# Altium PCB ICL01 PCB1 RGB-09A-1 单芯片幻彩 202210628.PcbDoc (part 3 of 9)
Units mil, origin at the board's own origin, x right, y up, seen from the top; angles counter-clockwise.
Board outline 17436.43 x 6581.89 mil, 2 copper layers (Top Layer, Bottom Layer), stack 65.792 mil thick; 425 components, 516 nets, 1625 pads, 2772 vias.
Unrouted connection lines stored in the file: 1.
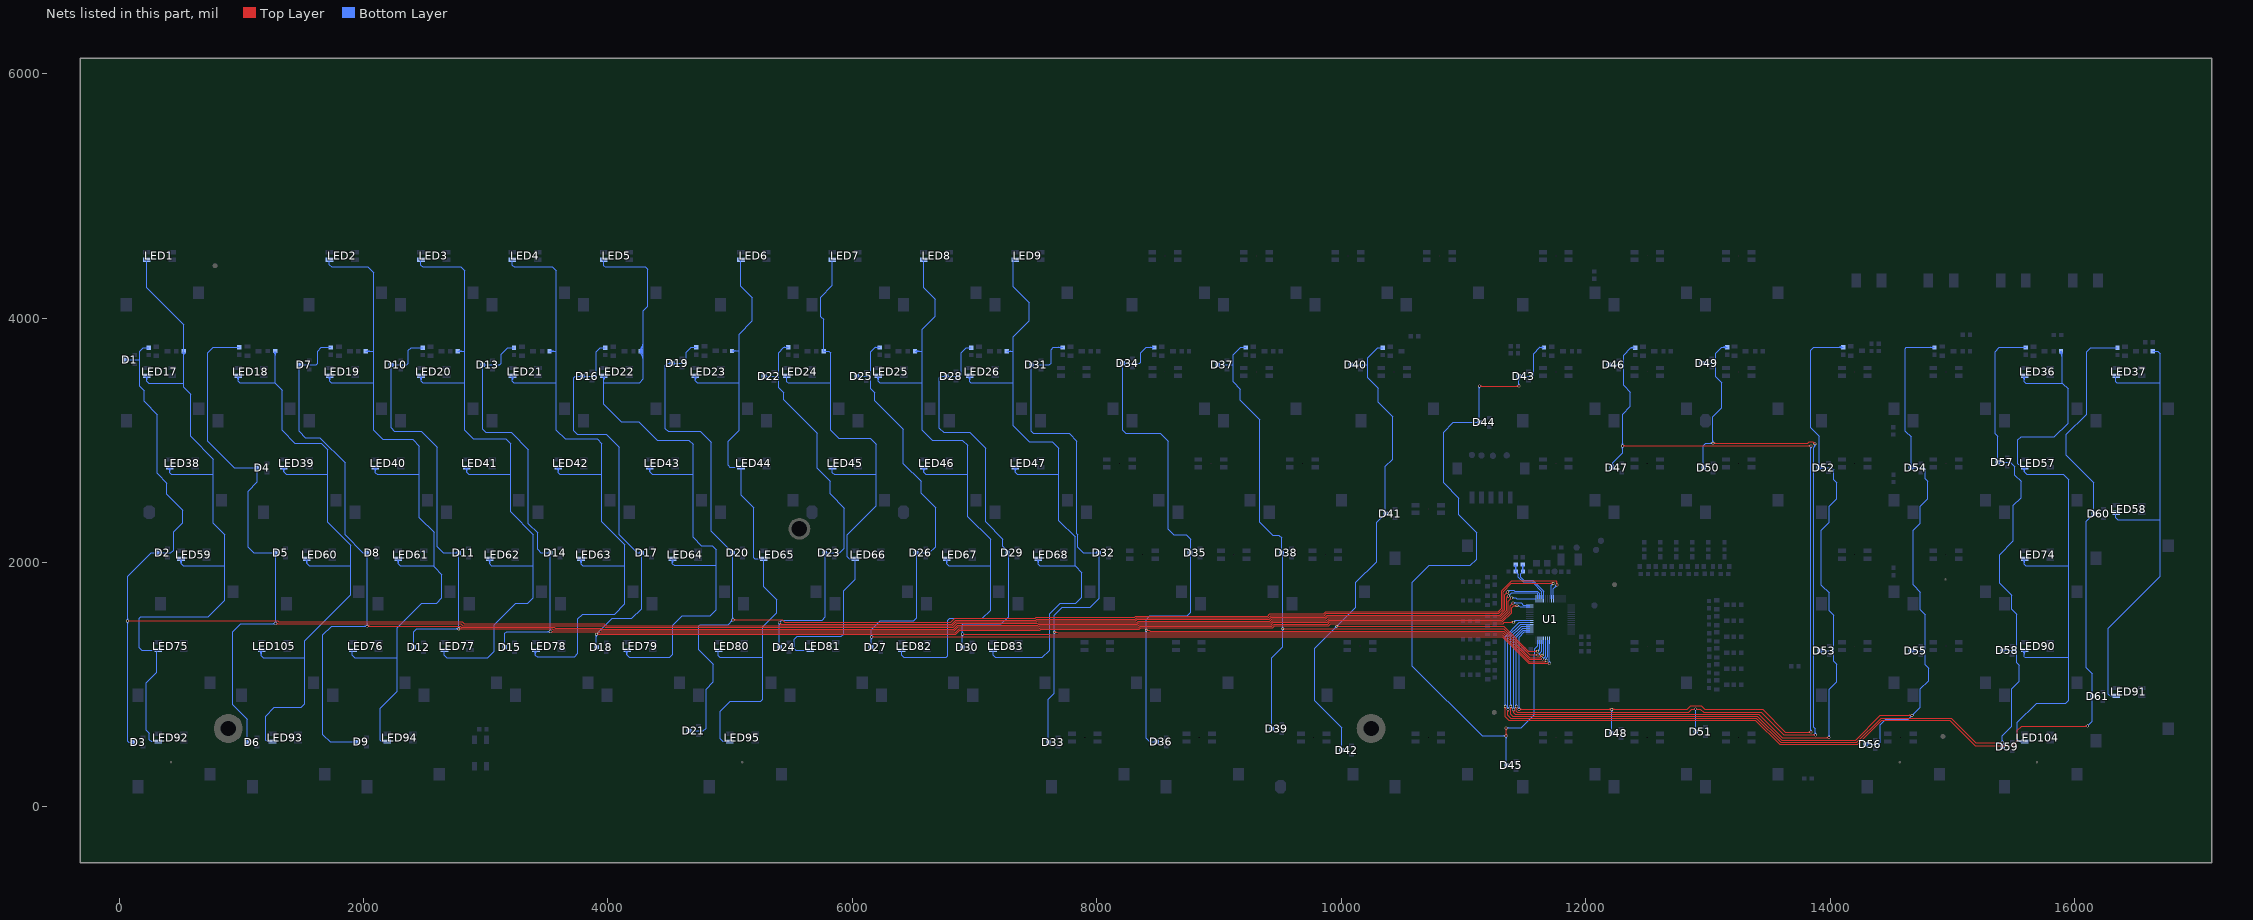
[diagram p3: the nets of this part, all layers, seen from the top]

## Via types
v1: diameter 23.62, hole 15.75, Top Layer to Bottom Layer, tented both sides, 2766 vias
v2: diameter 19.68, hole 11.81, Top Layer to Bottom Layer, tented both sides, 6 vias

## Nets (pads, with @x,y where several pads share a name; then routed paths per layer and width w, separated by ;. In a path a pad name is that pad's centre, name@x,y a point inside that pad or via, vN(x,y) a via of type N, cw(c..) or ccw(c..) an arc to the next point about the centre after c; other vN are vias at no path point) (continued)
CB19: LED36.VDD LED57.VDD LED74.VDD LED90.VDD LED104.VDD RC20.1 | length 5825.7
  Bottom Layer w7.87: LED104.VDD@15561.9,528.12 ccw(c15548.04,519.1) 15548.04,535.63 ; LED104.VDD@15561.9,543.15 cw(c15548.04,552.16) 15548.04,535.63 ; LED90.VDD@15577.48,1273.92 cw(c15553.96,1250.4) 15587.23,1250.4 cw(c15620.5,1250.4) LED90.VDD@15596.97,1273.92 ; LED74.VDD@15577.48,2021.95 cw(c15553.96,1998.43) 15587.23,1998.43 cw(c15620.5,1998.43) LED74.VDD@15596.97,2021.95 ; LED57.VDD@15577.48,2769.98 cw(c15553.96,2746.46) 15587.23,2746.46 cw(c15620.5,2746.46) LED57.VDD@15596.97,2769.98 ; LED36.VDD@15577.48,3518.01 cw(c15553.96,3494.49) 15587.23,3494.49 cw(c15620.5,3494.49) LED36.VDD@15596.97,3518.01 ; LED104.VDD@15587.23,535.63 15548.04,535.63 ; LED90.VDD@15587.23,1283.66 15587.23,1230.63 15594.44,1223.41 15951.76,1223.41 ; LED74.VDD@15587.23,2031.69 15587.23,1987.57 15601.86,1972.94 15951.84,1972.94 ; LED36.VDD@15587.23,3527.76 15587.23,3480.03 15599.12,3468.14 15898.16,3468.14 ; RC20.1@15878.89,3718.31 cw(c15832.39,3671.81) 15898.16,3671.81 ; RC20.1@15884.46,3723.88 cw(c15851.4,3690.82) 15898.16,3690.82 ; RC20.1@15888.64,3728.06 15898.16,3718.54 15898.16,3468.14 ; RC20.1@15890.03,3729.45 cw(c15870.41,3709.83) 15898.16,3709.83 ; 15548.04,535.63 15531.34,552.34 15531.34,691.28 15688.15,848.1 15925.86,848.1 15951.93,874.17 15951.93,2678.85 15908.95,2721.83 15609.49,2721.83 15587.23,2744.09 15587.23,2793.53 15549.14,2793.53 15536.68,2805.98 15536.68,3002.12 15562.17,3027.61 15833.9,3027.61 15946.53,3140.24 15946.53,3419.76 15898.16,3468.14
CB20: LED37.VDD LED58.VDD LED91.VDD RC21.1 | length 3932.8
  Bottom Layer w7.87: LED58.VDD@16335.26,2405.71 16335.26,2367.45 16351.29,2351.42 16702.21,2351.42 ; LED37.VDD@16335.26,3527.76 16335.26,3477.43 16344.16,3468.53 16702.31,3468.53 ; LED91.VDD@16340.18,909.65 16291,909.65 16277.09,923.56 16277.09,1462.83 16702.23,1887.97 16702.23,3706.02 16679.69,3728.56 RC21.1@16639.12,3728.56
CBL0: LED1.VDD LED17.VDD LED38.VDD LED59.VDD LED75.VDD LED92.VDD RC1.1 | length 6470.8
  Bottom Layer w7.87: LED17.VDD@217.25,3518.01 cw(c193.73,3494.49) 226.99,3494.49 cw(c260.26,3494.49) LED17.VDD@236.74,3518.01 ; LED1.VDD@226.01,4476.58 226.01,4246.62 529.38,3943.25 RC1.1@529.38,3729.04 ; LED17.VDD@226.99,3527.76 226.99,3483.24 241.8,3468.43 530.53,3468.43 531.38,3467.58 ; LED92.VDD@320.5,535.63 263.07,535.63 248.78,549.93 248.78,601.05 222.83,627 222.83,1015.02 308,1100.2 308,1271.35 320.5,1283.85 LED75.VDD@320.5,1283.66 188.02,1283.66 167.59,1304.09 167.59,1544.47 179.39,1556.27 731.13,1556.27 866.81,1691.95 866.81,2226.78 772.32,2321.27 772.32,2846.58 586.3,3032.6 586.3,3378.35 531.38,3433.27 531.38,3467.58 ; LED38.VDD@404.26,2769.98 cw(c380.73,2746.46) 414,2746.46 cw(c447.27,2746.46) LED38.VDD@423.74,2769.98 ; LED38.VDD@414,2779.73 414,2734.93 425.72,2723.22 772.31,2723.22 ; LED59.VDD@497.76,2021.95 cw(c474.24,1998.43) 507.5,1998.43 cw(c540.77,1998.43) LED59.VDD@517.25,2021.95 ; LED59.VDD@507.5,2031.69 507.5,1989.29 523.65,1973.15 866.01,1973.15 ; RC1.1@519.64,3719.3 cw(c491.29,3690.95) 531.38,3690.95 ; RC1.1@525.21,3724.87 cw(c510.3,3709.96) 531.38,3709.96 ; 531.38,3700.6 cw(c557.83,3700.6) RC1.1@539.13,3719.3 ; RC1.1@531.38,3729.04 531.38,3467.58
CBL1: LED18.VDD LED39.VDD LED60.VDD LED93.VDD LED105.VDD RC2.1 | length 5924.5
  Bottom Layer w7.87: LED18.VDD@965.28,3518.01 cw(c941.76,3494.49) 975.02,3494.49 cw(c1008.29,3494.49) LED18.VDD@984.77,3518.01 ; LED18.VDD@975.02,3527.76 975.02,3483.08 987.2,3470.9 1274.1,3470.9 1277.42,3467.59 ; LED105.VDD@1152.29,1273.92 cw(c1128.76,1250.4) 1162.03,1250.4 cw(c1195.3,1250.4) LED105.VDD@1171.77,1273.92 ; LED105.VDD@1162.03,1283.66 1162.03,1238.61 1180.68,1219.96 1520.4,1219.96 ; LED93.VDD@1231.37,526.58 ccw(c1211.46,509.21) 1211.46,535.63 ; LED93.VDD@1231.37,544.69 cw(c1211.46,562.05) 1211.46,535.63 ; LED93.VDD@1255.54,535.63 1211.46,535.63 ; RC2.1@1267.67,3720.28 cw(c1244.15,3696.76) 1277.42,3696.76 cw(c1310.68,3696.76) RC2.1@1287.16,3720.28 ; RC2.1@1277.42,3730.03 1277.42,3467.59 ; LED39.VDD@1339.3,2769.98 cw(c1315.77,2746.46) 1349.04,2746.46 cw(c1382.31,2746.46) LED39.VDD@1358.78,2769.98 ; LED39.VDD@1349.04,2779.73 1349.04,2740.31 1368.52,2720.83 1708.48,2720.83 ; LED60.VDD@1526.3,2021.95 cw(c1502.78,1998.43) 1536.05,1998.43 cw(c1569.31,1998.43) LED60.VDD@1545.79,2021.95 ; LED60.VDD@1536.05,2031.69 1536.05,1992.83 1555.99,1972.88 1894.87,1972.88 ; 1211.46,535.63 1199.63,547.46 1199.63,742.21 1271.9,814.48 1489.69,814.48 1520.35,845.15 1520.35,1360.52 1895.35,1735.52 1895.35,2142.15 1708.35,2329.16 1708.35,2920.36 1652.8,2975.91 1438.55,2975.91 1334.53,3079.92 1334.53,3410.47 1277.42,3467.59
CBL2: LED2.VDD LED19.VDD LED40.VDD LED61.VDD LED76.VDD LED94.VDD RC3.1 | length 6858.4
  Bottom Layer w7.87: LED19.VDD@1713.31,3518.01 cw(c1689.79,3494.49) 1723.06,3494.49 cw(c1756.32,3494.49) LED19.VDD@1732.8,3518.01 ; LED2.VDD@1722.07,4476.58 1722.07,4436.53 1739.72,4418.89 2033.38,4418.89 2082.21,4370.06 2082.21,3470.74 ; LED19.VDD@1723.06,3527.76 1723.06,3482.67 1734.99,3470.74 2082.21,3470.74 ; LED76.VDD@1910.06,1283.66 1910.06,1240.43 1929.33,1221.17 2275.49,1221.17 ; RC3.1@2018.56,3729.04 2081.92,3729.04 ; RC3.1@2028.3,3719.3 cw(c2051.82,3695.78) 2051.82,3729.04 cw(c2051.82,3762.31) RC3.1@2028.3,3738.79 ; LED40.VDD@2087.33,2769.98 cw(c2063.8,2746.46) 2097.07,2746.46 cw(c2130.34,2746.46) LED40.VDD@2106.81,2769.98 ; LED40.VDD@2097.07,2779.73 2097.07,2735.78 2112.73,2720.12 2455.14,2720.12 2456.38,2721.36 ; LED94.VDD@2166.24,526.77 ccw(c2147.23,510.81) 2147.23,535.63 ; LED94.VDD@2166.24,544.49 cw(c2147.23,560.46) 2147.23,535.63 ; LED94.VDD@2190.58,535.63 2147.23,535.63 ; LED61.VDD@2274.34,2021.95 cw(c2250.81,1998.43) 2284.08,1998.43 cw(c2317.35,1998.43) LED61.VDD@2293.82,2021.95 ; LED61.VDD@2284.08,2031.69 2284.08,1991.48 2301.42,1974.14 2576.83,1974.14 ; 2082.21,3470.74 2082.21,3083.91 2158.92,3007.2 2401.31,3007.2 2456.38,2952.13 2456.38,2721.36 ; 2147.23,535.63 2135.37,547.49 2135.37,806.72 2275.49,946.84 2275.49,1466.17 2476.06,1666.74 2599.09,1666.74 2642.4,1710.05 2642.4,1897.96 2577.22,1963.15 2577.22,2246.69 2456.38,2367.53 2456.38,2721.36
CBL3: LED3.VDD LED20.VDD LED41.VDD LED62.VDD LED77.VDD RC4.1 | length 6075.1
  Bottom Layer w7.87: LED20.VDD@2461.34,3518.01 cw(c2437.82,3494.49) 2471.09,3494.49 cw(c2504.35,3494.49) LED20.VDD@2480.83,3518.01 ; LED3.VDD@2470.1,4476.58 2470.1,4433.52 2483.79,4419.83 2796.33,4419.83 2829.26,4386.9 2829.26,3082.24 2899.92,3011.58 3165.05,3011.58 3203.42,2973.21 3203.42,2723.4 ; LED20.VDD@2471.09,3527.76 2471.09,3482.81 2483.05,3470.85 2826.68,3470.85 ; LED77.VDD@2663.02,1283.66 2663.02,1241.68 2682.18,1222.51 3016.65,1222.51 3069.18,1275.04 3069.18,1489.82 3246.1,1666.74 3346.14,1666.74 3390.43,1711.03 3390.43,2228.13 3203.42,2415.14 3203.42,2723.4 ; RC4.1@2770.53,3729.04 2828.96,3729.04 ; RC4.1@2780.27,3719.3 cw(c2803.79,3695.78) 2803.79,3729.04 cw(c2803.79,3762.31) RC4.1@2780.27,3738.79 ; LED41.VDD@2835.36,2769.98 cw(c2811.84,2746.46) 2845.1,2746.46 cw(c2878.37,2746.46) LED41.VDD@2854.85,2769.98 ; LED41.VDD@2845.1,2779.73 2845.1,2740.05 2862.39,2722.77 3202.79,2722.77 3203.42,2723.4 ; LED62.VDD@3022.37,2021.95 cw(c2998.84,1998.43) 3032.11,1998.43 cw(c3065.38,1998.43) LED62.VDD@3041.85,2021.95 ; LED62.VDD@3032.11,2031.69 3032.11,1989.77 3047.26,1974.62 3390.03,1974.62
CBL4: LED4.VDD LED21.VDD LED42.VDD LED63.VDD LED78.VDD RC5.1 | length 6199.6
  Bottom Layer w7.87: LED21.VDD@3209.37,3518.01 cw(c3185.85,3494.49) 3219.12,3494.49 cw(c3252.39,3494.49) LED21.VDD@3228.86,3518.01 ; LED4.VDD@3218.13,4476.58 3218.13,4433.33 3232.7,4418.76 3545.23,4418.76 3578.27,4385.72 3578.27,3083.23 3649.02,3012.48 3911.13,3012.48 3951.46,2972.15 3951.46,2721.72 ; LED21.VDD@3219.12,3527.76 3219.12,3482.98 3230.78,3471.32 3577.07,3471.32 ; LED78.VDD@3396.38,1273.92 cw(c3372.86,1250.4) 3406.13,1250.4 cw(c3439.39,1250.4) LED78.VDD@3415.87,1273.92 ; LED78.VDD@3406.13,1283.66 3406.13,1242.94 3420.58,1228.48 3726.75,1228.48 3754.04,1255.78 3754.04,1538.04 3794.24,1578.24 4056.33,1578.24 4139.45,1661.36 4139.45,2145.06 3951.46,2333.05 3951.46,2721.72 ; RC5.1@3522.49,3729.04 3577.98,3729.04 ; RC5.1@3532.24,3719.3 cw(c3555.76,3695.78) 3555.76,3729.04 cw(c3555.76,3762.31) RC5.1@3532.24,3738.79 ; LED42.VDD@3583.39,2769.98 cw(c3559.87,2746.46) 3593.13,2746.46 cw(c3626.4,2746.46) LED42.VDD@3602.88,2769.98 ; LED42.VDD@3593.13,2779.73 3593.13,2735.53 3606.95,2721.72 3951.46,2721.72 ; LED63.VDD@3770.4,2021.95 cw(c3746.88,1998.43) 3780.14,1998.43 cw(c3813.41,1998.43) LED63.VDD@3789.89,2021.95 ; LED63.VDD@3780.14,2031.69 3780.14,1987.42 3794.18,1973.39 4138.93,1973.39
CBL5: LED5.VDD LED22.VDD LED43.VDD LED64.VDD LED79.VDD RC6.1 | length 6937.9
  Bottom Layer w7.87: LED22.VDD@3957.41,3518.01 cw(c3933.88,3494.49) 3967.15,3494.49 cw(c4000.42,3494.49) LED22.VDD@3976.89,3518.01 ; LED5.VDD@3966.17,4476.58 3966.17,4428.78 3976.86,4418.08 4305.91,4418.08 4326.46,4397.54 4326.46,4094.89 4291.17,4059.61 4291.17,3727.76 ; LED22.VDD@3967.15,3527.76 3967.15,3295.73 4109.93,3152.95 4252.64,3152.95 4403.74,3001.86 4663.05,3001.86 4699.49,2965.42 4699.49,2204.92 4765.66,2138.74 4854.87,2138.74 4887.48,2106.14 4887.48,1612.44 4838.44,1563.4 4609.02,1563.4 4531.18,1485.56 4531.18,1248.25 4507.67,1224.73 4174.58,1224.73 4154.16,1245.15 LED79.VDD@4154.16,1283.66 ; 3967.33,3471.21 4259.99,3471.21 4291.17,3502.39 4291.17,3727.76 ; LED79.VDD@4144.41,1273.92 cw(c4120.89,1250.4) 4154.16,1250.4 cw(c4187.42,1250.4) LED79.VDD@4163.9,1273.92 ; RC6.1@4259.8,3719.3 cw(c4184.06,3643.56) 4291.17,3643.56 ; RC6.1@4259.8,3738.79 ccw(c4184.06,3814.53) 4291.17,3814.53 ; RC6.1@4265.37,3724.87 cw(c4203.07,3662.57) 4291.17,3662.57 ; RC6.1@4265.37,3733.22 ccw(c4203.07,3795.52) 4291.17,3795.52 ; RC6.1@4270.82,3727.76 4291.17,3727.76 ; RC6.1@4270.93,3727.65 ccw(c4222.07,3776.51) 4291.17,3776.51 ; RC6.1@4270.93,3730.43 cw(c4222.07,3681.58) 4291.17,3681.58 ; RC6.1@4276.5,3722.08 ccw(c4241.08,3757.5) 4291.17,3757.5 ; RC6.1@4276.5,3736 cw(c4241.08,3700.59) 4291.17,3700.59 ; RC6.1@4281.48,3722.16 cw(c4291.17,3716.58) 4291.17,3727.76 ; RC6.1@4282.07,3716.52 ccw(c4260.09,3738.49) 4291.17,3738.49 ; RC6.1@4282.07,3741.57 cw(c4260.09,3719.6) 4291.17,3719.6 ; RC6.1@4282.46,3733.83 ccw(c4291.17,3737.05) 4291.17,3727.76 ; LED43.VDD@4331.42,2769.98 cw(c4307.9,2746.46) 4341.17,2746.46 cw(c4374.43,2746.46) LED43.VDD@4350.91,2769.98 ; LED43.VDD@4341.17,2779.73 4341.17,2740.35 4361.02,2720.5 4697.94,2720.5 ; LED64.VDD@4518.43,2021.95 cw(c4494.91,1998.43) 4528.17,1998.43 cw(c4561.44,1998.43) LED64.VDD@4537.92,2021.95 ; LED64.VDD@4528.17,2031.69 4528.17,1989.1 4540.85,1976.43 4887.04,1976.43
CBL6: LED6.VDD LED23.VDD LED44.VDD LED65.VDD LED80.VDD LED95.VDD RC7.1 | length 5717.4
  Bottom Layer w7.87: LED23.VDD@4705.44,3518.01 cw(c4681.91,3494.49) 4715.18,3494.49 cw(c4748.45,3494.49) LED23.VDD@4724.92,3518.01 ; LED23.VDD@4715.18,3527.76 4715.18,3485.66 4731.02,3469.82 5068.36,3469.82 5073.35,3474.81 ; LED80.VDD@4902.19,1283.66 4902.19,1237.81 4916.67,1223.33 5267.58,1223.33 ; LED95.VDD@4995.69,535.63 4940.27,535.63 4918.36,557.54 4918.36,781.61 4999.49,862.74 5248.97,862.74 5267.62,881.38 5267.62,1473.06 5382.82,1588.27 5382.82,1694.03 5276.21,1800.64 LED65.VDD@5276.21,2031.69 5202.39,2031.69 5193.62,2040.47 5193.62,2446.93 5089.2,2551.35 LED44.VDD@5089.2,2779.73 4997.18,2779.73 4983.25,2793.66 4983.25,2992.14 5073.35,3082.24 5073.35,3474.81 ; RC7.1@5014.62,3730.53 5073.16,3730.53 ; RC7.1@5024.36,3720.78 cw(c5047.89,3697.26) 5047.89,3730.53 cw(c5047.89,3763.79) RC7.1@5024.36,3740.27 ; LED6.VDD@5088.21,4476.58 5088.21,4259.81 5182.52,4165.5 5182.52,3976.54 5073.35,3867.38 5073.35,3474.81
CBL7: LED7.VDD LED24.VDD LED45.VDD LED66.VDD LED81.VDD RC8.1 | length 5109.3
  Bottom Layer w7.87: LED24.VDD@5463.21,3527.76 5463.21,3480.63 5473.7,3470.15 5820.82,3470.15 ; LED81.VDD@5655.14,1283.66 5536.97,1283.66 5525.21,1295.43 5525.21,1373.97 5548.25,1397.02 5910.1,1397.02 5927.56,1414.48 5927.56,1767.15 6024.24,1863.83 LED66.VDD@6024.24,2031.69 5975.45,2031.69 5958.95,2048.19 5958.95,2228.12 6195.55,2464.72 6195.55,2967.38 6146.64,3016.29 5889.31,3016.29 5822.37,3083.23 5822.37,3714.63 5808.44,3728.56 RC8.1@5764.62,3728.56 5764.62,3989.36 5741.69,4012.29 5741.69,4171.86 5836.24,4266.42 LED7.VDD@5836.24,4476.58 ; LED45.VDD@5837.23,2779.73 5837.23,2735.79 5852.44,2720.57 6195.42,2720.57
CBL8: LED8.VDD LED25.VDD LED46.VDD LED67.VDD LED82.VDD RC9.1 | length 5924.5
  Bottom Layer w7.87: LED25.VDD@6201.5,3518.01 cw(c6177.98,3494.49) 6211.24,3494.49 cw(c6244.51,3494.49) LED25.VDD@6220.99,3518.01 ; LED25.VDD@6211.24,3527.76 6211.24,3481.85 6223.68,3469.42 6570.18,3469.42 ; LED82.VDD@6403.17,1283.66 6403.17,1239.57 6419.72,1223.03 6766.19,1223.03 6780.02,1236.86 6780.02,1527.27 6795.78,1543.02 7063.85,1543.02 7130.59,1609.77 7130.59,2188.86 6943.58,2375.87 6943.58,2957.14 6898.76,3001.96 6651.67,3001.96 6570.4,3083.23 6570.4,3908.72 6677.83,4016.15 6677.83,4153.68 6584.28,4247.23 LED8.VDD@6584.28,4476.58 ; RC9.1@6512.65,3728.06 6570.11,3728.06 ; RC9.1@6522.39,3718.32 cw(c6545.92,3694.79) 6545.92,3728.06 cw(c6545.92,3761.33) RC9.1@6522.39,3737.8 ; LED46.VDD@6575.52,2769.98 cw(c6551.99,2746.46) 6585.26,2746.46 cw(c6618.53,2746.46) LED46.VDD@6595,2769.98 ; LED46.VDD@6585.26,2779.73 6585.26,2739.05 6602.05,2722.26 6942.72,2722.26 ; LED67.VDD@6762.52,2021.95 cw(c6739,1998.43) 6772.27,1998.43 cw(c6805.54,1998.43) LED67.VDD@6782.01,2021.95 ; LED67.VDD@6772.27,2031.69 6772.27,1988.15 6787.07,1973.35 7130.06,1973.35
CBL9: LED9.VDD LED26.VDD LED47.VDD LED68.VDD LED83.VDD RC10.1 | length 5801.3
  Bottom Layer w7.87: LED26.VDD@6949.53,3518.01 cw(c6926.01,3494.49) 6959.28,3494.49 cw(c6992.54,3494.49) LED26.VDD@6969.02,3518.01 ; LED26.VDD@6959.28,3527.76 6959.28,3478.74 6968.46,3469.55 7316.04,3469.55 ; LED83.VDD@7151.21,1283.66 7151.21,1242.95 7170.47,1223.68 7555.16,1223.68 7615.03,1283.55 7615.03,1580.32 7702.44,1667.72 7829.41,1667.72 7878.62,1716.94 7878.62,1915.16 7822.31,1971.47 ; RC10.1@7262.95,3727.76 7316.46,3727.76 ; RC10.1@7272.4,3718.31 cw(c7295.21,3695.5) 7295.21,3727.76 ; RC10.1@7272.4,3737.8 ccw(c7296.63,3762.03) 7296.63,3727.76 ; LED47.VDD@7323.55,2769.98 cw(c7300.02,2746.46) 7333.29,2746.46 cw(c7366.56,2746.46) LED47.VDD@7343.03,2769.98 ; LED9.VDD@7332.31,4476.58 7316.59,4460.86 7316.59,4254.51 7447.43,4123.67 7447.43,3976.14 7316.46,3845.18 7316.46,3727.76 ; LED47.VDD@7333.29,2779.73 7333.29,2737.71 7350.7,2720.3 7690.12,2720.3 ; LED68.VDD@7510.56,2021.95 cw(c7487.03,1998.43) 7520.3,1998.43 cw(c7553.57,1998.43) LED68.VDD@7530.04,2021.95 ; LED68.VDD@7520.3,2031.69 7520.3,1986.85 7533.53,1973.62 7822.31,1973.62 7822.31,2211.24 7690.63,2342.92 7690.63,2933.66 7635.94,2988.35 7446.03,2988.35 7316.46,3117.92 7316.46,3727.76
CC1: 
CL0: D1.A D2.A D3.A RL19.1 U1.51 | length 15840.2
  Top Layer w7.87: v1(69.98,1521.42) 1297.1,1521.42 1304.97,1513.55 2806.85,1513.55 2822.6,1497.79 3970.98,1497.79 3986.62,1482.16 6817.91,1482.16 6850.84,1515.1 7506.64,1515.1 7514.34,1522.79 8320.37,1522.79 8331.44,1533.87 9409.92,1533.87 9427.58,1551.53 9867.39,1551.53 9884.82,1568.96 11294.99,1568.96 11339.36,1613.33 11339.36,1736.74 v1(11361.77,1759.15) ; v1@75.54,1515.85 cw(c88.99,1502.41) 88.99,1521.42 cw(c88.99,1540.43) v1@75.54,1526.99 ; v1@11353.9,1759.15 cw(c11334.89,1759.15) 11348.33,1745.7 cw(c11361.77,1732.26) v1@11361.77,1751.27
  Bottom Layer w7.87: D1.A@49.23,3659.22 169.29,3659.22 ; v1@64.41,1515.85 cw(c50.94,1502.38) 69.99,1502.38 ; v1@64.41,1526.99 ccw(c50.94,1540.46) 69.99,1540.46 ; 69.99,1502.44 cw(c88.96,1502.44) v1@75.54,1515.85 ; 69.99,1540.4 ccw(c88.96,1540.4) v1@75.54,1526.99 ; D3.A@116.69,530.53 78.69,530.53 69.99,539.23 69.99,1886.62 262.8,2079.44 D2.A@317.95,2079.44 424.59,2079.44 446.99,2101.84 446.99,2250.86 520.2,2324.07 520.2,2427.9 391.84,2556.26 391.84,2650.11 313.66,2728.29 313.66,3209.06 205.39,3317.33 205.39,3406.2 169.29,3442.3 169.29,3729.54 197.22,3757.46 RL19.1@242.98,3757.46 ; v1(11361.77,1759.15) 11376.38,1773.75 11410.19,1773.75 11417.78,1766.15 11604.53,1766.15 11624.68,1745.99 U1.51@11624.68,1703.16 ; v1@11361.77,1767.02 ccw(c11361.77,1786.03) 11375.21,1772.59 ccw(c11388.66,1759.15) v1@11369.65,1759.15
CL1: D4.A D5.A D6.A RL20.1 U1.50 | length 15038.5
  Top Layer w7.87: v1(1281.21,1499.67) 2796.7,1499.67 2812.45,1483.92 3960.57,1483.92 3976.21,1468.29 6823.65,1468.29 6856.59,1501.22 7512.39,1501.22 7520.09,1508.92 8326.11,1508.92 8337.19,1519.99 9415.67,1519.99 9433.32,1537.65 9873.14,1537.65 9890.57,1555.09 11300.74,1555.09 11353.24,1607.59 11353.24,1710.29 ; v1@1286.78,1494.1 cw(c1300.22,1480.66) 1300.22,1499.67 cw(c1300.22,1518.68) v1@1286.78,1505.24 ; 11356.17,1713.22 cw(c11367.08,1702.31) v1@11367.08,1717.74 ; v1@11359.21,1725.37 cw(c11338.81,1724.73) 11353.24,1710.29 ; v1@11367.82,1724.87 11353.24,1710.29
  Bottom Layer w7.87: RL20.1@985.11,3759.92 769.97,3759.92 727.78,3717.72 727.78,2991.54 944.31,2775.01 D4.A@1130.31,2775.01 1130.31,2658.92 1055.68,2584.29 1055.68,2126.46 1102.7,2079.44 D5.A@1281.48,2079.44 1281.48,1499.3 996.67,1499.3 931.62,1434.25 931.62,837.77 1050,719.4 D6.A@1050,530 ; 1261.31,1499.3 ccw(c1261.31,1519.57) 1275.64,1505.24 ccw(c1261.57,1519.32) 1281.48,1519.32 ; 1263.09,1499.3 cw(c1263.09,1481.55) v1@1275.64,1494.1 ; 1281.48,1518.05 ccw(c1299.59,1518.05) v1@1286.78,1505.24 ; v1(11367.08,1725.61) 11368.56,1725.61 11395.22,1752.28 11598.78,1752.28 11608.94,1742.12 U1.50@11608.94,1703.16 ; v1@11367.08,1733.49 ccw(c11367.08,1756.08) 11383.05,1740.1 ; v1@11374.95,1725.61 cw(c11390.38,1725.61) 11379.47,1736.53
CL2: D7.A D8.A D9.A RL21.1 U1.49 | length 14219.7
  Top Layer w7.87: v1(2030.68,1477.92) 2793.82,1477.92 2801.7,1470.05 3559.73,1470.05 3567.49,1462.29 3951.25,1462.29 3959.13,1454.41 6829.4,1454.41 6862.33,1487.35 7518.14,1487.35 7525.84,1495.05 8331.86,1495.05 8342.93,1506.12 9421.41,1506.12 9439.07,1523.78 9878.88,1523.78 9896.32,1541.21 11306.48,1541.21 11367.11,1601.84 11367.11,1684.34 v1(11393.85,1711.08) ; v1@2036.25,1472.36 cw(c2049.69,1458.92) 2049.69,1477.92 cw(c2049.69,1496.93) v1@2036.25,1483.49 ; v1@11385.98,1711.08 cw(c11366.97,1711.08) 11380.41,1697.64 cw(c11393.85,1684.2) v1@11393.85,1703.21
  Bottom Layer w7.87: RL21.1@1732.16,3758.93 1656.41,3758.93 1625.7,3728.21 1625.7,3629.91 1612.65,3616.87 D7.A@1475.75,3616.87 1475.75,3071.73 1525.34,3022.15 1644.33,3022.15 1850.53,2815.95 1850.53,2224.95 1996.05,2079.44 D8.A@2030.61,2079.44 2030.61,1477.84 1738.57,1477.84 1668.31,1407.58 1668.31,590.07 1726.94,531.43 D9.A@1943.64,531.43 ; 2011.47,1477.84 ccw(c2011.47,1497.14) 2025.11,1483.49 ccw(c2011.83,1496.78) 2030.61,1496.78 ; 2011.87,1477.84 cw(c2011.87,1459.12) v1@2025.11,1472.36 ; 2030.61,1497.09 ccw(c2049.85,1497.09) v1@2036.25,1483.49 ; v1(11393.85,1711.08) 11429.25,1711.08 11437.17,1703.16 U1.49@11593.19,1703.16 ; v1@11399.42,1705.51 cw(c11412.86,1692.07) 11412.86,1711.08 cw(c11412.86,1730.09) v1@11399.42,1716.65
CL3: D10.A D11.A D12.A RL22.1 U1.48 | length 12528.5
  Top Layer w7.87: v1(2779.8,1456.18) 3546.53,1456.17 3554.29,1448.41 3937.03,1448.41 3944.91,1440.54 6835.15,1440.54 6868.08,1473.47 7523.88,1473.47 7531.58,1481.17 8337.61,1481.17 8348.68,1492.25 9427.16,1492.25 9444.82,1509.9 9884.63,1509.9 9902.06,1527.34 11312.23,1527.34 11380.99,1596.09 11380.99,1644.01 v1(11406.18,1669.2) ; v1@2785.36,1450.61 cw(c2798.79,1437.18) 2798.79,1456.17 cw(c2798.82,1475.2) v1@2785.36,1461.74 ; v1@11398.31,1669.2 cw(c11379.3,1669.2) 11392.74,1655.76 cw(c11406.18,1642.32) v1@11406.18,1661.33
  Bottom Layer w7.87: D12.A@2411.9,1306.47 2411.9,1432.17 2435.91,1456.18 v1(2779.8,1456.18) D11.A@2779.8,2079.44 2651.93,2079.44 2604.11,2127.26 2604.11,2227.92 2605.74,2229.55 2605.74,2943.34 2473.87,3075.2 2251.73,3075.2 2225.38,3101.56 D10.A@2225.38,3616.87 2354.24,3616.87 2367.65,3630.28 2367.65,3734.76 2390.84,3757.95 RL22.1@2486.09,3757.95 ; v1@2774.23,1450.61 ccw(c2760.79,1437.17) 2760.79,1456.18 ccw(c2760.79,1475.19) 2774.23,1461.74 ccw(c2760.79,1475.19) 2779.8,1475.19 ccw(c2798.8,1475.19) v1@2785.36,1461.74 ; v1(11406.18,1669.2) 11473.01,1669.2 11490.23,1651.98 U1.48@11542.01,1651.98 ; v1@11411.75,1663.63 cw(c11425.19,1650.19) 11425.19,1669.2 cw(c11425.19,1688.21) v1@11411.75,1674.77
CL4: D13.A D14.A D15.A RL23.1 U1.47 | length 11703.6
  Top Layer w7.87: v1@3528.64,1434.54 3924.72,1434.54 3932.59,1426.66 6840.89,1426.66 6873.83,1459.6 7529.63,1459.6 7537.33,1467.3 8343.35,1467.3 8354.43,1478.37 9432.91,1478.37 9450.57,1496.03 9890.38,1496.03 9907.81,1513.46 11317.98,1513.46 11394.86,1590.35 11394.86,1630.29 11410.43,1645.86 v1(11436.7,1645.86) ; v1@3534.21,1428.86 cw(c3547.93,1415.14) 3547.93,1434.54 ; v1@3534.21,1439.99 ccw(c3547.38,1453.16) 3547.38,1434.54 ; v1@11431.14,1640.3 ccw(c11417.69,1626.85) 11417.69,1645.86 ccw(c11417.69,1664.87) v1@11431.14,1651.43
  Bottom Layer w7.87: D15.A@3156.32,1306.47 3156.32,1419.11 3171.63,1434.42 v1(3528.64,1434.42) D14.A@3528.64,2079.44 3451.2,2079.44 3424.06,2106.58 3424.06,2243.07 3348.83,2318.3 3348.83,2924.34 3208.14,3065.03 3001.77,3065.03 2976.25,3090.56 D13.A@2976.25,3616.87 3113.31,3616.87 3127.97,3631.53 3127.97,3703.7 3182.23,3757.95 RL23.1@3232.16,3757.95 ; v1@3523.07,1428.86 ccw(c3509.63,1415.41) 3509.63,1434.42 ccw(c3509.63,1453.43) 3523.07,1439.99 ccw(c3509.63,1453.43) 3528.64,1453.43 ccw(c3547.65,1453.43) v1@3534.21,1439.99 ; v1(11436.7,1645.86) 11453.28,1645.86 ; v1@11442.81,1640.89 cw(c11453.28,1632.36) 11453.28,1645.86 ; v1@11442.81,1650.84 ccw(c11453.28,1659.37) 11453.28,1645.86 ; U1.47@11542.01,1636.23 11462.91,1636.23 11453.28,1645.86
CL5: D16.A D17.A D18.A RL24.1 U1.40 | length 11146.7
  Top Layer w7.87: v1(3905.84,1412.79) 6846.64,1412.79 6879.57,1445.73 7535.38,1445.73 7543.08,1453.42 8349.1,1453.42 8360.17,1464.5 9438.65,1464.5 9456.31,1482.16 9896.12,1482.16 9913.56,1499.59 11323.72,1499.59 11334.86,1510.73 v1(11408.73,1510.73) ; v1@3911.41,1407.22 cw(c3924.85,1393.78) 3924.85,1412.79 cw(c3924.85,1431.8) v1@3911.41,1418.36 ; v1@11403.16,1505.16 ccw(c11389.72,1491.72) 11389.72,1510.73 ccw(c11389.72,1529.74) v1@11403.16,1516.3
  Bottom Layer w7.87: v1@3900.28,1407.22 cw(c3887.01,1393.96) 3905.77,1393.96 ; D18.A@3905.77,1306.47 v1(3905.84,1412.79) ; 3905.77,1393.6 cw(c3925.03,1393.6) v1@3911.41,1407.22 ; v1(3905.84,1412.79) 4035.29,1542.24 4196.1,1542.24 4276.47,1622.6 D17.A@4276.47,2079.44 4239.78,2079.44 4093.59,2225.64 4093.59,2943.92 3988.3,3049.21 3750.8,3049.21 3721.23,3078.77 3721.23,3511.25 3734.01,3524.02 D16.A@3790.04,3524.02 3896.79,3524.02 3905.19,3532.42 3905.19,3723.83 3939.32,3757.95 RL24.1@3978.22,3757.95 ; v1@3905.84,1420.66 ccw(c3905.84,1439.67) 3919.29,1426.23 ccw(c3932.73,1412.79) v1@3913.72,1412.79 ; v1(11408.73,1510.73) 11423.99,1525.99 U1.40@11542.01,1525.99 ; v1@11408.73,1518.6 ccw(c11408.73,1537.61) 11422.17,1524.17 ccw(c11435.61,1510.73) v1@11416.6,1510.73
CL6: D19.A D20.A D21.A RL25.1 U1.58 | length 11467.1
  Top Layer w7.87: v1(5021.98,1530.53) 5424.55,1530.54 5445.18,1509.91 6806.41,1509.91 6839.35,1542.84 7495.15,1542.84 7502.85,1550.54 8308.87,1550.54 8319.95,1561.62 9398.43,1561.62 9416.08,1579.27 9855.9,1579.27 9873.33,1596.71 11283.5,1596.71 11311.62,1624.83 11311.62,1768.21 11393.69,1850.29 11757.36,1850.29 11764.67,1842.98 v1(11764.67,1814.61) ; v1@5027.55,1524.96 cw(c5041.01,1511.5) 5041.01,1530.54 ; v1@5027.55,1536.09 ccw(c5040.97,1549.52) 5040.97,1530.54 ; v1@11759.1,1820.17 ccw(c11745.66,1833.61) 11764.67,1833.61 ccw(c11783.68,1833.61) v1@11770.24,1820.17
  Bottom Layer w7.87: D21.A@4662.33,623.75 4781.02,623.75 4802.83,645.56 4802.83,963 4862.87,1023.04 4862.87,1166.74 4743.96,1285.65 4743.96,1481.48 4754.51,1492.02 4983.48,1492.02 v1(5021.98,1530.53) D20.A@5021.98,2079.44 4844.76,2256.67 4844.76,2983.71 4755.57,3072.9 4491.72,3072.9 4468.71,3095.91 4468.71,3612.32 4486.72,3630.32 D19.A@4525.63,3630.32 4635.14,3630.32 4641.42,3636.6 4641.42,3718.9 4682.43,3759.92 RL25.1@4722.31,3759.92 ; v1@5014.11,1530.53 cw(c4995.1,1530.53) 5008.54,1517.09 cw(c5021.98,1503.64) v1@5021.98,1522.65 ; v1@5016.41,1536.09 ccw(c5002.97,1549.54) 5021.98,1549.54 ccw(c5040.99,1549.54) v1@5027.55,1536.09 ; U1.58@11734.92,1703.16 11734.92,1784.86 v1(11764.67,1814.61) ; v1@11756.79,1814.61 cw(c11737.78,1814.61) 11751.23,1801.16 cw(c11764.67,1787.72) v1@11764.67,1806.73
CL7: D22.A D23.A D24.A RL26.1 U1.57 | length 10230.6
  Top Layer w7.87: v1(5402.81,1508.79) 5415.56,1496.03 ; v1@5403.1,1500.92 cw(c5403.74,1484.21) 5415.56,1496.03 ; v1@5410.67,1508.49 ccw(c5427.38,1507.86) 5415.56,1496.03 ; v1@11729.08,1822.97 ccw(c11715.64,1809.53) 11715.64,1828.54 ccw(c11715.64,1847.55) v1@11729.08,1834.11 ; v1(11734.65,1828.54) 11391.57,1828.54 11325.49,1762.46 11325.49,1619.08 11289.24,1582.83 9879.08,1582.83 9861.64,1565.4 9421.83,1565.4 9404.17,1547.74 8325.69,1547.74 8314.62,1536.67 7508.6,1536.67 7500.9,1528.97 6845.09,1528.97 6812.16,1496.03 5415.56,1496.03
  Bottom Layer w7.87: D22.A@5278.17,3523.04 5396.48,3523.04 ; v1@5397.24,1503.22 cw(c5383.84,1489.82) 5402.79,1489.82 ; D24.A@5402.79,1306.47 5402.79,1509.23 5422.46,1528.9 5753.52,1528.9 5779.75,1555.13 5779.75,2071.88 D23.A@5772.19,2079.44 5895.99,2079.44 5934.54,2117.99 5934.54,2444.93 5817.52,2561.95 5817.52,2664.11 5711.23,2770.4 5711.23,3057.71 5437.12,3331.82 5437.12,3390.51 5396.48,3431.15 5396.48,3523.04 ; 5402.79,1489.73 cw(c5421.86,1489.73) v1@5408.37,1503.22 ; v1@5402.81,1516.66 ccw(c5402.81,1534.55) 5415.46,1521.9 ; v1@5410.68,1508.79 cw(c5430.81,1508.79) 5416.57,1523.02 ; RL26.1@5465.52,3750.17 ccw(c5442,3726.65) 5442,3759.92 ccw(c5442,3793.18) RL26.1@5465.52,3769.66 ; RL26.1@5475.27,3759.92 5440.3,3759.92 5396.48,3716.09 5396.48,3523.04 ; U1.57@11719.17,1703.16 11719.17,1813.07 v1(11734.65,1828.54) ; v1@11726.77,1828.54 cw(c11707.76,1828.54) 11721.2,1815.1 cw(c11734.65,1801.66) v1@11734.65,1820.67
CL8: D25.A D26.A D27.A RL27.1 U1.25 | length 9377
  Top Layer w7.87: v1(6156.4,1391.04) 11315.95,1391.04 11532.51,1174.48 v1(11703.42,1174.48) v1@11706.94,1174.48 ; v1@6161.97,1385.47 cw(c6175.41,1372.03) 6175.41,1391.04 cw(c6175.41,1410.05) v1@6161.97,1396.61 ; v1@11697.86,1168.92 ccw(c11684.41,1155.47) 11684.41,1174.48 ccw(c11684.41,1193.49) v1@11697.86,1180.05
  Bottom Layer w7.87: D25.A@6034.13,3523.04 6151.26,3523.04 ; D25.A@6045.73,3513.02 cw(c6069.92,3488.82) 6069.92,3523.04 cw(c6069.92,3557.26) D25.A@6045.73,3533.06 ; v1@6150.83,1385.47 cw(c6137.5,1372.14) 6156.36,1372.14 ; v1@6150.83,1396.61 ccw(c6137.5,1409.94) 6156.36,1409.94 ; D27.A@6156.36,1306.47 6156.36,1450.92 6227.82,1522.39 6500.84,1522.39 6527.83,1549.38 6527.83,2071.29 D26.A@6519.67,2079.44 6631.05,2079.44 6682.3,2130.7 6682.3,2448.15 6564.01,2566.44 6564.01,2662.77 6418.02,2808.77 6418.02,3091.43 6184.17,3325.28 6184.17,3387.37 6151.26,3420.29 6151.26,3523.04 ; 6156.36,1371.93 cw(c6175.52,1371.93) v1@6161.97,1385.47 ; 6156.36,1410.16 ccw(c6175.52,1410.16) v1@6161.97,1396.61 ; RL27.1@6213.56,3749.19 ccw(c6190.03,3725.67) 6190.03,3758.93 ccw(c6190.03,3792.2) RL27.1@6213.56,3768.68 ; RL27.1@6223.3,3758.93 6185.38,3758.93 6151.26,3724.81 6151.26,3523.04 ; v1@11697.86,1180.05 ccw(c11684.41,1193.49) 11703.42,1193.49 ccw(c11722.43,1193.49) v1@11708.99,1180.05 ; v1(11703.42,1174.48) U1.25@11703.42,1364.57
CL9: D28.A D29.A D30.A RL28.1 U1.26 | length 8584.6
  Top Layer w7.87: v1@6898.95,1412.31 7613.01,1412.31 7615.37,1409.95 11316.66,1409.95 11537.75,1188.87 11667.43,1188.87 ; v1@6905.03,1407.6 cw(c6916.4,1396.23) 6916.4,1412.31 ; v1@6905.03,1418.74 ccw(c6920.54,1434.25) 6920.54,1412.31 ; 11653.11,1188.87 ccw(c11653.11,1223.43) v1(11677.55,1198.99) 11667.43,1188.87 ; v1@11669.87,1197.27 cw(c11661.01,1195.28) 11667.43,1188.87 ; v1@11675.83,1191.31 ccw(c11673.85,1182.45) 11667.43,1188.87
  Bottom Layer w7.87: D28.A@6768.51,3524.02 6878.67,3524.02 6890.7,3536.05 6890.7,3717.2 6931.44,3757.95 RL28.1@6973.3,3757.95 ; D28.A@6768.51,3524.33 6724.92,3524.33 6712.54,3511.95 6712.54,3098.9 6746.08,3065.36 6960.06,3065.36 7089.56,2935.86 7089.56,2333.28 7230.8,2192.04 7230.8,2131.12 7278.14,2083.79 7278.14,2049.93 ; v1@6893.9,1407.6 cw(c6881.93,1395.63) 6898.85,1395.63 ; v1@6893.9,1418.74 ccw(c6881.93,1430.7) 6898.85,1430.7 ; D30.A@6898.85,1306.47 6898.85,1490.83 6905.47,1497.45 7218.66,1497.45 7278.2,1556.99 7278.2,2049.93 ; 6898.85,1392.68 cw(c6919.95,1392.68) v1@6905.03,1407.6 ; 6898.85,1433.65 ccw(c6919.95,1433.65) v1@6905.03,1418.74 ; v1@11671.99,1204.56 ccw(c11658.54,1218) 11677.55,1218 ccw(c11696.56,1218) v1@11683.12,1204.56 ; v1(11677.55,1198.99) 11677.55,1219.25 11687.68,1229.37 U1.26@11687.68,1364.57
  other v1: 6899.46,1413.17
CL10: D31.A D32.A D33.A RL29.1 U1.27 | length 8720.5
  Top Layer w7.87: v2(7652.54,1430.55) 7676.52,1430.55 7683.24,1423.83 11322.41,1423.83 11537.71,1208.52 11645.7,1208.52 v1(11647.79,1210.61) ; v2@7656.72,1426.37 cw(c7666.8,1416.29) 7666.8,1430.55 cw(c7666.8,1444.81) v2@7656.72,1434.72 ; 11623.74,1208.52 ccw(c11623.74,1234.67) v1@11642.23,1216.18 ; 11633.83,1208.52 cw(c11633.83,1196.65) v1@11642.23,1205.05
  Bottom Layer w7.87: D33.A@7602.81,530.23 7602.81,879.8 7652.34,929.33 v2@7652.34,1424.62 ; v2@7648.37,1434.72 ccw(c7638.73,1444.36) 7652.36,1444.36 ; 7652.36,1411 7652.36,1568.22 7716.53,1632.39 7946.69,1632.39 8021.5,1707.2 8021.5,2072.71 D32.A@8014.77,2079.44 7889.05,2079.44 7845.18,2123.31 7845.18,2228.54 7837.36,2236.36 7837.36,2993.61 7774.51,3056.47 7478.6,3056.47 7462.87,3072.2 7462.87,3616.26 D31.A@7463.87,3617.26 7611.83,3617.26 7625.31,3630.74 7625.31,3740.17 7644.08,3758.93 RL29.1@7720.35,3758.93 ; 7652.34,1415.81 cw(c7667.28,1415.81) 7656.72,1426.37 ccw(c7667.24,1415.85) 7652.36,1415.85 ; 7652.36,1445.25 ccw(c7667.24,1445.25) v2@7656.72,1434.72 ; RL29.1@7710.6,3749.19 ccw(c7687.08,3725.67) 7687.08,3758.93 ccw(c7687.08,3792.2) RL29.1@7710.6,3768.68 ; v1(11647.79,1210.61) 11671.93,1234.75 U1.27@11671.93,1364.57 ; v1@11647.79,1218.49 ccw(c11647.79,1237.5) 11661.24,1224.06 ccw(c11674.68,1210.61) v1@11655.67,1210.61 ; v2@7648.37,1426.37 cw(c7638.73,1416.74) 7652.36,1416.74 ccw(c7638.76,1416.77) v2@7648.37,1426.37
CL11: D34.A D35.A D36.A RL30.1 U1.28 | length 7959.6
  Top Layer w7.87: v2(8403.16,1444.53) 8429.63,1444.53 8436.45,1437.7 11328.16,1437.7 11543.46,1222.4 11622.7,1222.4 v1(11641.26,1240.95) ; v2@8407.34,1440.35 cw(c8417.42,1430.27) 8417.42,1444.53 cw(c8417.42,1458.78) v2@8407.34,1448.7 ; v1@11633.38,1240.95 cw(c11614.37,1240.95) 11627.82,1227.51 cw(c11641.26,1214.07) v1@11641.26,1233.08
  Bottom Layer w7.87: v2@8398.99,1440.35 cw(c8389.32,1430.68) 8402.99,1430.68 ; v2@8398.99,1448.7 ccw(c8389.32,1458.37) 8402.99,1458.37 ; 8402.99,1429.86 cw(c8417.83,1429.86) v2@8407.34,1440.35 ; 8402.99,1459.19 ccw(c8417.83,1459.19) v2@8407.34,1448.7 ; RL30.1@8459.62,3749.19 ccw(c8436.1,3725.67) 8436.1,3758.93 ccw(c8436.1,3792.2) RL30.1@8459.62,3768.68 ; RL30.1@8469.36,3758.93 8404.01,3758.93 8360.87,3715.79 8360.87,3637.44 8353.33,3629.91 8210.9,3629.91 8210.9,3082.56 8237.32,3056.14 8520.08,3056.14 8583.25,2992.96 8583.25,2272.95 8627.54,2228.66 8731.66,2228.66 8770.59,2189.73 8770.59,1593.13 8741.36,1563.89 8434.98,1563.89 8402.99,1531.91 8402.99,563.6 8434.29,532.29 D36.A@8488.54,532.29 ; v1(11641.26,1240.95) 11656.18,1255.88 U1.28@11656.18,1364.57 ; v1@11641.26,1248.83 ccw(c11641.26,1267.84) 11654.7,1254.4 ccw(c11668.14,1240.95) v1@11649.13,1240.95
CL12: D37.A D38.A D39.A RL31.1 U1.29 | length 5988.6
  Top Layer w7.87: v2(9519.87,1457.74) 11327.74,1457.74 11541.92,1243.56 v1@11611.78,1243.56 ; v2@9524.04,1453.56 cw(c9534.13,1443.48) 9534.13,1457.74 cw(c9534.13,1471.99) v2@9524.04,1461.91 ; 11590.77,1243.56 ccw(c11590.77,1264.57) v1@11605.63,1249.71 ; 11593.6,1243.56 cw(c11593.6,1226.56) v1@11605.63,1238.58
  Bottom Layer w7.87: D37.A@8986.26,3616.87 9115.81,3616.87 ; RL31.1@9218.38,3758.93 9176.52,3758.93 9115.81,3698.22 9115.81,3616.87 ; D39.A@9432.75,641.2 9432.75,1222.43 9519.94,1309.61 9519.94,2071.26 D38.A@9511.76,2079.44 9511.76,2202.52 9490.07,2224.2 9437.57,2224.2 9332.73,2329.03 9332.73,3167.65 9173.84,3326.55 9173.84,3418.93 9115.81,3476.97 9115.81,3616.87 ; v2@9515.69,1453.56 cw(c9505.45,1443.32) 9519.94,1443.32 ; v2@9515.69,1461.91 ccw(c9505.45,1472.15) 9519.94,1472.15 ; 9519.94,1443.64 cw(c9533.97,1443.64) v2@9524.04,1453.56 ; 9519.94,1471.83 ccw(c9533.97,1471.83) v2@9524.04,1461.91 ; v1(11611.19,1244.15) 11640.43,1273.38 U1.29@11640.43,1364.57 ; v1@11611.19,1252.02 ccw(c11611.19,1271.03) 11624.64,1257.59 ccw(c11638.08,1244.15) v1@11619.07,1244.15
CL13: D40.A D41.A D42.A RL32.1 U1.30 | length 5895.9
  Top Layer w7.87: v2(9962.78,1477.72) 11327.38,1477.72 11531.49,1273.61 v1(11605.65,1273.61) ; v2@9966.95,1473.54 cw(c9977.03,1463.46) 9977.03,1477.72 cw(c9977.03,1491.97) v2@9966.95,1481.89 ; v1@11600.08,1268.04 ccw(c11586.64,1254.6) 11586.64,1273.61 ccw(c11586.64,1292.62) v1@11600.08,1279.18
  Bottom Layer w7.87: 9952.3,1466.68 ccw(c9941.27,1477.72) v2@9956.87,1477.72 ; 9953.65,1468.03 cw(c9962.78,1458.9) v2@9962.78,1471.81 ; v2@9962.78,1483.62 ccw(c9962.78,1499.22) 9973.81,1488.19 ; v2@9968.68,1477.72 cw(c9981.6,1477.72) 9972.46,1486.85 ; D42.A@10003,465.17 10003,649.66 9784.08,868.58 9784.08,1298.46 10119.69,1634.07 10119.69,1836.71 10290.68,2007.69 10290.68,2330.53 D41.A@10360.8,2400.65 10360.8,2786.79 10419.66,2845.66 10419.66,3193.78 10302.83,3310.61 10302.83,3426.55 10216.09,3513.3 10216.09,3617.04 ; D40.A@10078.34,3616.87 10215.92,3616.87 10216.09,3617.04 ; RL32.1@10339.44,3757.95 10300.54,3757.95 10216.09,3673.5 10216.09,3617.04 ; v1(11605.65,1273.61) 11624.68,1292.64 U1.30@11624.68,1364.57 ; v1@11605.65,1281.48 ccw(c11605.65,1300.49) 11619.09,1287.05 ccw(c11632.54,1273.61) v1@11613.53,1273.61
CL14: D43.A D44.A D45.A RL33.1 U1.31 | length 6508.5
  Top Layer w7.87: v1(11130.03,3443.48) v1(11452.98,3443.48) ; v1@11135.6,3437.92 cw(c11149.04,3424.48) 11149.04,3443.48 cw(c11149.04,3462.49) v1@11135.6,3449.05 ; v1@11343.55,586.68 ccw(c11330.11,600.12) 11349.12,600.12 ccw(c11368.13,600.12) v1@11354.69,586.68 ; v1@11343.55,639.77 cw(c11330.11,626.33) 11349.12,626.33 cw(c11368.13,626.33) v1@11354.69,639.77 ; v1(11349.12,581.11) v1(11349.12,645.34) ; v1@11447.41,3437.92 ccw(c11433.97,3424.48) 11433.97,3443.48 ccw(c11433.97,3462.49) v1@11447.41,3449.05
  Bottom Layer w7.87: v1@11124.47,3437.92 cw(c11111.02,3424.48) 11130.03,3424.48 cw(c11149.04,3424.48) v1@11135.6,3437.92 ; v1(11130.03,3443.48) D44.A@11130.03,3146.24 10917.07,3146.24 10837.17,3066.34 10837.17,2651.66 10963.13,2525.7 10963.13,2388.79 11106.97,2244.96 11106.97,2027.49 11055.64,1976.17 10718.62,1976.17 10580.39,1837.94 10580.39,1152.5 11151.78,581.11 v1(11349.12,581.11) D45.A@11349.12,339.63 ; v1@11343.55,586.68 cw(c11330.11,600.12) 11330.11,581.11 cw(c11330.11,562.1) 11343.55,575.54 cw(c11330.11,562.1) 11349.12,562.1 cw(c11368.13,562.1) v1@11354.69,575.54 ; v1@11349.12,646.06 11472.92,646.06 11579.46,752.6 11579.46,1250.37 11583.9,1254.81 11583.9,1292.51 11608.94,1317.55 U1.31@11608.94,1364.57 ; v1@11354.69,639.77 cw(c11369.88,624.58) 11369.88,646.06 ; v1@11354.69,650.91 ccw(c11366.38,662.59) 11366.38,646.06 ; D43.A@11442.67,3513.95 cw(c11418.34,3489.62) 11452.74,3489.62 ; v1@11447.41,3449.05 ccw(c11434.54,3461.92) 11452.74,3461.92 ; v1@11452.74,3443.91 11452.74,3524.02 11564.39,3524.02 11574.07,3533.71 11574.07,3707.23 11625.78,3758.93 ; 11452.74,3463.07 ccw(c11472.56,3463.07) v1@11458.55,3449.05 ; 11452.74,3489.88 cw(c11486.77,3489.88) D43.A@11462.71,3513.95 ; D43.A@11464.28,3513.95 cw(c11488.61,3489.62) 11488.61,3524.02 ; D43.A@11464.28,3533.99 ccw(c11488.35,3558.05) 11488.35,3524.02 ; RL33.1@11648.45,3749.34 ccw(c11625.78,3727.35) 11625.78,3758.93 ; RL33.1@11648.45,3768.53 cw(c11625.78,3790.51) 11625.78,3758.93 ; RL33.1@11658.34,3758.93 11625.78,3758.93
CL15: D46.A D47.A D48.A RL34.1 U1.34 | length 8994.6
  Top Layer w7.87: v1(11454.64,797.65) v1(12213.27,797.65) 12830.78,797.65 12861.29,828.15 12944.89,828.15 12975.4,797.65 13448.3,797.65 13633.34,612.61 v1(13843.19,612.61) ; v1@11460.21,792.08 cw(c11473.64,778.64) 11473.64,797.65 cw(c11473.65,816.66) v1@11460.21,803.22 ; v1@12207.7,792.08 ccw(c12194.26,778.64) 12194.26,797.65 ccw(c12194.26,816.66) v1@12207.7,803.21 ; v1@12218.83,792.08 cw(c12232.28,778.64) 12232.28,797.65 cw(c12232.28,816.66) v1@12218.83,803.21 ; v1@12301.01,2954.14 v1(13843.19,2954.14) ; v1@12306,2948.25 cw(c12320.21,2934.04) 12320.21,2954.14 ; v1@12306,2959.39 ccw(c12318.67,2972.06) 12318.67,2954.14 ; v1@13837.62,607.04 ccw(c13824.18,593.6) 13824.18,612.61 ccw(c13824.18,631.62) v1@13837.62,618.17 ; v1@13837.62,2948.57 ccw(c13824.18,2935.13) 13824.18,2954.14 ccw(c13824.18,2973.15) v1@13837.62,2959.71
  Bottom Layer w7.87: v1@11449.07,803.22 ccw(c11435.63,816.66) 11454.64,816.66 ccw(c11473.65,816.66) v1@11460.21,803.22 ; v1(11454.64,797.65) 11454.64,1387.44 11498.7,1431.5 U1.34@11542.01,1431.5 ; D46.A@12189.77,3616.87 12309.36,3616.87 ; D47.A@12207.14,2785.03 ccw(c12176.81,2815.36) 12219.71,2815.36 ; v1@12207.7,792.08 cw(c12194.26,778.64) 12213.27,778.64 cw(c12232.28,778.64) v1@12218.83,792.08 ; D47.A@12212.71,2779.46 ccw(c12195.82,2796.35) 12219.71,2796.35 ; D48.A@12213.27,601.95 v1(12213.27,797.65) ; D47.A@12215.59,2775.01 12219.71,2779.12 12219.71,2817.72 12301.21,2899.23 12301.21,3214.33 12364.41,3277.53 12364.41,3393.06 12309.38,3448.09 12309.38,3696.91 12370.42,3757.95 RL34.1@12404.4,3757.95 ; 12219.71,2803.09 ccw(c12245.24,2803.09) D47.A@12227.19,2785.03 ; v1@12294.86,2948.25 cw(c12279.53,2932.92) 12301.21,2932.92 ; v1@12294.86,2959.39 ccw(c12279.53,2974.72) 12301.21,2974.72 ; 12301.21,2936.7 cw(c12317.55,2936.7) v1@12306,2948.25 ; 12301.21,2970.94 ccw(c12317.55,2970.94) v1@12306,2959.39 ; RL34.1@12394.66,3748.21 ccw(c12371.13,3724.68) 12371.13,3757.95 ccw(c12371.13,3791.22) RL34.1@12394.66,3767.69 ; v1@13837.62,618.17 ccw(c13824.18,631.62) 13843.19,631.62 ccw(c13862.2,631.62) v1@13848.75,618.17 ; v1@13837.62,2948.57 cw(c13824.18,2935.13) 13843.19,2935.13 cw(c13862.2,2935.13) v1@13848.75,2948.57 ; v1(13843.19,612.61) v1(13843.19,2954.14)
  other v1: 12300.43,2953.82
CL16: D49.A D50.A D51.A RL35.1 U1.35 | length 8419
  Top Layer w7.87: v1@11426.43,817.26 cw(c11412.99,803.82) 11432,803.82 cw(c11451.01,803.82) v1@11437.57,817.26 ; v1(11432,822.83) 11432,784.81 11441.8,775.01 12842.73,775.01 12867.99,800.27 12938.67,800.27 12963.93,775.01 13434.72,775.01 13619.76,589.97 v1(13879.25,589.97) ; v1(13040.04,2975.79) 13816.5,2975.79 13828.52,2987.81 13858.28,2987.81 v1(13874.67,2971.42) ; v1@13045.61,2970.23 cw(c13059.05,2956.79) 13059.05,2975.79 cw(c13059.05,2994.8) v1@13045.61,2981.36 ; v1@13866.8,2971.42 ccw(c13847.79,2971.42) 13861.23,2984.86 ccw(c13874.67,2998.3) v1@13874.67,2979.29 ; v1@13873.68,584.4 ccw(c13860.24,570.96) 13860.24,589.97 ccw(c13860.24,608.98) v1@13873.68,595.54
  Bottom Layer w7.87: v1@11426.43,828.39 ccw(c11412.99,841.83) 11432,841.83 ccw(c11451.01,841.83) v1@11437.57,828.39 ; v1(11432,822.83) 11432,1388.43 11490.82,1447.25 U1.35@11542.01,1447.25 ; D51.A@12899.64,615.69 v1(12899.64,800.68) ; D49.A@12950.83,3630.32 13064.03,3630.32 ; D50.A@12952.61,2785.03 ccw(c12928.42,2809.22) 12962.64,2809.22 ccw(c12996.85,2809.22) D50.A@12972.66,2785.03 ; D49.A@12962.42,3620.3 cw(c12986.62,3596.11) 12986.62,3630.32 cw(c12986.62,3664.54) D49.A@12962.42,3640.34 ; D50.A@12962.64,2775.01 12962.64,2955.5 12982.93,2975.79 v1(13040.04,2975.79) 13040.04,3191.35 13113.49,3264.79 13113.49,3471.46 13064.36,3520.58 13064.36,3713.7 13111.56,3760.9 RL35.1@13157.35,3760.9 ; v1@13034.47,2970.23 ccw(c13021.03,2956.79) 13021.03,2975.79 ccw(c13021.03,2994.8) 13034.47,2981.36 ccw(c13021.03,2994.8) 13040.04,2994.8 ccw(c13059.05,2994.8) v1@13045.61,2981.36 ; RL35.1@13147.61,3751.16 ccw(c13124.09,3727.63) 13124.09,3760.9 ccw(c13124.09,3794.17) RL35.1@13147.61,3770.64 ; v1@13869.1,2965.85 cw(c13855.66,2952.41) 13874.67,2952.41 cw(c13893.68,2952.41) v1@13880.24,2965.85 ; v1@13873.68,595.54 ccw(c13860.24,608.98) 13879.25,608.98 ccw(c13898.26,608.98) v1@13884.81,595.54 ; v1(13874.67,2971.42) 13874.67,2950.32 13864.84,2940.49 13864.84,653.91 13879.25,639.5 v1(13879.25,589.97)
CL17: D52.A D53.A RL36.1 U1.36 | length 7638.5
  Top Layer w7.87: v1@11403.8,792.08 cw(c11390.35,778.64) 11409.36,778.64 cw(c11428.37,778.64) v1@11414.93,792.08 ; v1(11409.36,797.65) 11409.36,771.09 11422.18,758.28 13415.04,758.28 13605.98,567.33 v1(13990.83,567.33) ; v1@13985.26,561.76 ccw(c13971.82,548.32) 13971.82,567.33 ccw(c13971.82,586.34) v1@13985.26,572.9
  Bottom Layer w7.87: v1@11403.8,803.22 ccw(c11390.35,816.66) 11409.36,816.66 ccw(c11428.37,816.66) v1@11414.93,803.22 ; v1(11409.36,797.65) 11409.36,1388.43 11483.94,1463 U1.36@11542.01,1463 ; D52.A@13897.77,2785.54 ccw(c13862.36,2820.95) 13912.44,2820.95 ; D52.A@13903.34,2779.97 ccw(c13881.37,2801.94) 13912.44,2801.94 ; D53.A@13912.09,1278.94 14028.23,1278.94 ; 13912.44,2798.51 ccw(c13930.79,2798.51) 13917.81,2785.54 ccw(c13943.23,2810.95) 13943.23,2775.01 ; D52.A@13917.81,2765.49 cw(c13940.79,2742.52) 13940.79,2775.01 ; D53.A@13923.68,1268.92 cw(c13947.88,1244.73) 13947.88,1278.94 cw(c13947.88,1313.16) D53.A@13923.68,1288.97 ; v1@13985.26,572.9 ccw(c13971.82,586.34) 13990.83,586.34 ccw(c14009.83,586.34) v1@13996.39,572.9 ; v1(13990.83,567.33) 13990.83,961.03 14053.82,1024.02 14053.82,1166.74 14029.21,1191.35 14029.21,1568.32 13990.83,1606.7 13990.83,1752.37 13927.83,1815.36 13927.83,2265.5 13990.83,2328.49 13990.83,2459.06 14052.83,2521.07 14052.83,2652.96 14028.23,2677.56 14028.23,2756.99 14010.21,2775.01 13912.44,2775.01 13912.44,3031.7 13842.35,3101.79 13842.35,3737.63 13865.62,3760.9 RL36.1@14106.17,3760.9 ; RL36.1@14096.43,3751.16 ccw(c14072.91,3727.63) 14072.91,3760.9 ccw(c14072.91,3794.17) RL36.1@14096.43,3770.64
CL18: D54.A D55.A D56.A RL37.1 U1.37 | length 8918.3
  Top Layer w7.87: v1@11381.16,817.26 cw(c11367.72,803.82) 11386.73,803.82 cw(c11405.74,803.82) v1@11392.29,817.26 ; v1(11386.73,822.83) 11386.73,758.99 11404.17,741.54 13405.2,741.54 13602.05,544.69 14207.36,544.69 14411.1,748.43 v1@14669.35,748.43 ; 14648.8,748.43 cw(c14648.8,727.75) v1@14663.43,742.37 ; 14651.17,748.43 ccw(c14651.17,765.77) v1@14663.43,753.51
  Bottom Layer w7.87: v1@11381.16,828.39 ccw(c11367.72,841.83) 11386.73,841.83 ccw(c11405.74,841.83) v1@11392.29,828.39 ; v1(11386.73,822.83) 11386.73,1390.4 11475.08,1478.75 U1.37@11542.01,1478.75 ; D56.A@14288.42,511.23 14391.42,511.23 14409.13,528.94 14409.13,671.66 14455.55,718.08 14639.83,718.08 14738.86,817.11 14738.86,966.94 14805.79,1033.87 14805.79,1136.31 14779.21,1162.88 14779.21,1574.22 14738.86,1614.57 14738.86,1757.29 14679.8,1816.35 14679.8,2263.91 14738.86,2322.97 14738.86,2459.06 14799.88,2520.09 14799.88,2662.8 14779.39,2683.29 14779.39,2760.04 14764.42,2775.01 D54.A@14661.46,2775.01 14661.46,3026.94 14612.95,3075.44 14612.95,3749.36 14622.53,3758.93 RL37.1@14853.22,3758.93 ; D56.A@14300.02,501.21 cw(c14324.22,477.01) 14324.22,511.23 cw(c14324.22,545.44) D56.A@14300.02,521.25 ; D54.A@14651.43,2785.03 ccw(c14627.24,2809.22) 14661.46,2809.22 ccw(c14695.67,2809.22) D54.A@14671.48,2785.03 ; 14655.07,733.32 ccw(c14640.45,747.94) v1@14661.12,747.94 ; 14656.73,734.99 cw(c14669,722.73) v1@14669,740.07 ; D55.A@14661.1,1278.94 14779.21,1278.94 ; v1@14669,755.82 ccw(c14669,776.49) 14683.62,761.87 ; D55.A@14672.7,1268.92 cw(c14696.89,1244.73) 14696.89,1278.94 cw(c14696.89,1313.16) D55.A@14672.7,1288.97 ; D54.A@14673.05,2764.99 cw(c14697.25,2740.79) 14697.25,2775.01 cw(c14697.25,2809.22) D54.A@14673.05,2785.03 ; v1@14676.87,747.94 cw(c14694.21,747.94) 14681.95,760.2 ; RL37.1@14843.48,3749.19 ccw(c14819.95,3725.67) 14819.95,3758.93 ccw(c14819.95,3792.2) RL37.1@14843.48,3768.68
  other v1: 14669,747.94
CL19: D57.A D58.A D59.A RL38.1 U1.38 | length 9274.9
  Top Layer w7.87: v1@11358.52,792.08 cw(c11345.08,778.64) 11364.09,778.64 cw(c11383.1,778.64) v1@11369.66,792.08 ; v1(11364.09,797.65) 11364.09,750.23 11388.52,725.79 13396.34,725.79 13594.17,527.96 14218.19,527.96 14416.02,725.79 14989.84,725.79 15189.64,525.99 v1(15409.49,525.99) ; v1@15403.92,520.42 ccw(c15390.48,506.98) 15390.48,525.99 ccw(c15390.48,545) v1@15403.92,531.56
  Bottom Layer w7.87: v1@11358.52,803.22 ccw(c11345.08,816.66) 11364.09,816.66 ccw(c11383.1,816.66) v1@11369.66,803.22 ; v1(11364.09,797.65) 11364.09,1391.38 11467.2,1494.5 U1.38@11542.01,1494.5 ; v1@15403.92,520.42 cw(c15390.48,506.98) 15409.49,506.98 cw(c15428.5,506.98) v1@15415.05,520.42 ; v1@15403.92,531.56 ccw(c15390.48,545) 15409.49,545 ccw(c15428.5,545) v1@15415.05,531.56 ; D58.A@15408.15,1279.93 15527.24,1279.93 ; D59.A@15409.49,494.5 15409.49,584.42 15486.89,661.82 15486.89,964.97 15548.9,1026.98 15548.9,1159.85 15527.24,1181.5 15527.24,1576.19 15486.89,1616.54 15486.89,1731.02 15388.2,1829.7 15388.2,2065.09 15499.38,2176.27 15499.38,2468.6 15561.88,2531.11 15561.88,2664.47 15511.23,2715.12 15511.23,2784.23 15474.8,2820.65 15369.49,2820.65 15369.49,3032.64 15349.16,3052.97 15349.16,3724.82 15383.27,3758.93 RL38.1@15601.25,3758.93
CL20: D60.A D61.A RL39.1 U1.39 | length 9717.6
  Top Layer w7.87: v1@11335.88,817.26 cw(c11322.44,803.82) 11341.45,803.82 cw(c11360.46,803.82) v1@11347.02,817.26 ; v1(11341.45,822.83) 11341.45,739.62 11371.03,710.05 13387.48,710.05 13586.3,511.23 14225.08,511.23 14423.9,710.05 14980,710.05 15188.59,501.46 15490.72,501.46 15531.34,542.08 15531.34,627.04 15566.12,661.82 v1(16104.73,661.82) ; v1@16099.16,656.25 ccw(c16085.72,642.81) 16085.72,661.82 ccw(c16085.72,680.83) v1@16099.16,667.39
  Bottom Layer w7.87: v1@11335.88,828.39 ccw(c11322.44,841.83) 11341.45,841.83 ccw(c11360.46,841.83) v1@11347.02,828.39 ; v1(11341.45,822.83) 11341.45,1394.33 11457.36,1510.24 U1.39@11542.01,1510.24 ; v1(16104.73,661.82) 16142.4,699.49 16142.4,1091 16095.63,1137.77 16095.63,2338.12 D60.A@16157.52,2400.01 16157.52,2652.14 15931.05,2878.61 15931.05,3047.9 16097.28,3214.13 16097.28,3723.23 16132,3757.95 RL39.1@16350.27,3757.95 ; v1@16104.73,669.69 ccw(c16104.73,688.7) 16118.17,675.26 ccw(c16131.61,661.82) v1@16112.6,661.82
CL21: 
COL1: 
COL2: 
COL3: 
COL4: 
COL5: 
COL6: 
COL7: 
COL8: 
COL9: 
COL10: 
COL11: 
COL12: 
COL13: 
COL14: 
COL15: 
D+: 
D+/CLK: CA5.1 RA2.2 U1.52 | length 434.1
  Bottom Layer w7.87: CA5.1@11428.47,1926.02 11449.93,1904.57 11449.93,1879.46 11487.21,1842.18 11560.59,1842.18 11640.43,1762.34 U1.52@11640.43,1703.16
  Bottom Layer w11.81: RA2.2@11419.74,1975.46 cw(c11398.65,1954.37) 11428.47,1954.37 ; CA5.1@11428.47,1926.02 RA2.2@11428.47,1983.04
D+_1: 
D-: 
D-/DATA: CA4.1 RA3.2 U1.53 | length 408.4
  Bottom Layer w7.87: CA4.1@11486.59,1926.02 11468.58,1908.01 11468.58,1880.44 11492.96,1856.06 11566.34,1856.06 11656.18,1766.22 U1.53@11656.18,1703.16
  Bottom Layer w11.81: CA4.1@11486.59,1926.02 RA3.2@11486.59,1983.39
D-_1: 
EB: 
EG: 
ER: 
